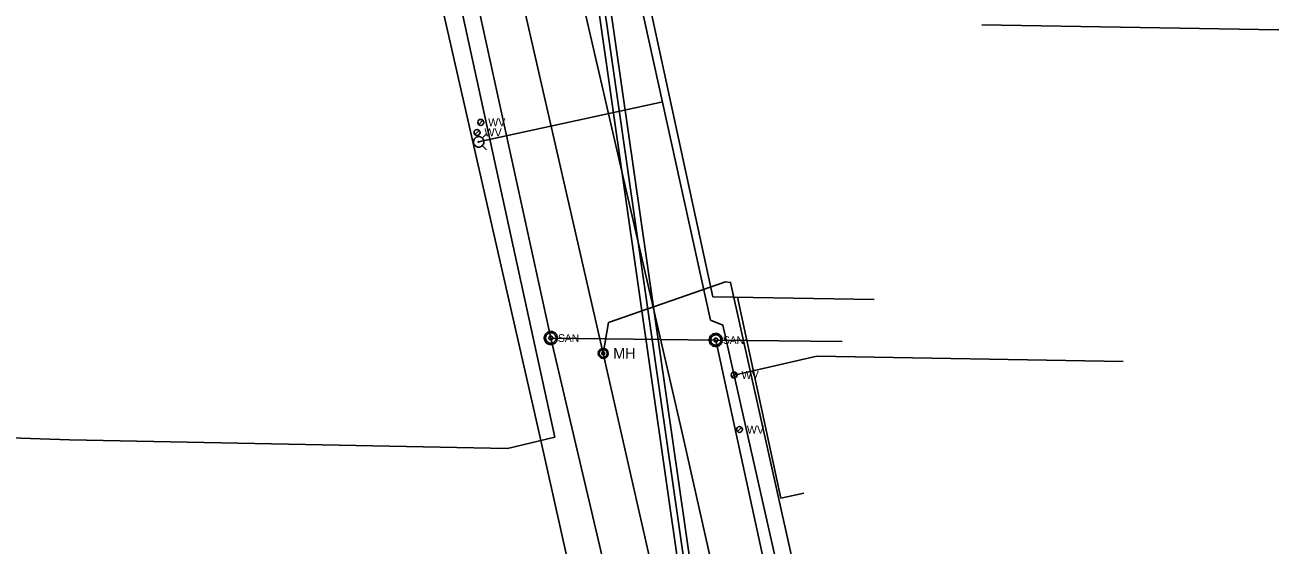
# Model space of a CAD drawing. Extents: x 596028 to 606371, y 330010 to 403088.
# Drawn here: x 604586 to 605210, y 338728 to 338989 of the extents above; entities that cross this region are included whole.
import ezdxf

# ---------------------------------------------------------------- set-up
doc = ezdxf.new("R2010")
doc.units = 0
for name, color, linetype in [('Default', 7, 'Continuous'), ('E_UTL_E', 7, 'Continuous'), ('E_UTL_E_UG', 7, 'Continuous'), ('E_UTL_G_UG', 7, 'Continuous'), ('E_UTL_Overhead', 7, 'Continuous'), ('E_UTL_SAN_MH', 7, 'Continuous'), ('E_UTL_SAN_UG', 7, 'Continuous'), ('E_UTL_SAN_UG_MMSD', 7, 'Continuous'), ('E_UTL_SAN_UG_OUTER_LIMITS', 7, 'Continuous'), ('E_UTL_T_UG', 7, 'Continuous'), ('E_UTL_TV_UG', 7, 'Continuous'), ('E_UTL_W', 7, 'Continuous'), ('E_UTL_W_UG', 7, 'Continuous'), ('E_UTL_WHydrant', 7, 'Continuous')]:
    doc.layers.add(name, color=color, linetype=linetype)

# ---------------------------------------------------------------- blocks, each defined once
blk = doc.blocks.new('MH')
at = {"layer": 'Default'}
for radius in [15.2, 12.2, 4.57]:
    blk.add_circle((0, 0), radius, dxfattribs=at)
blk.add_text('MH', height=32.92, dxfattribs=at).set_placement((30.5, -16.5))
blk = doc.blocks.new('WV')
at = {"layer": 'E_UTL_W'}
blk.add_line((-8.6, -8.6), (8.6, 8.6), dxfattribs=at)
blk.add_circle((0, 0), 12.2, dxfattribs=at)
blk.add_text('WV', height=32.92, dxfattribs=at).set_placement((30.5, -16.5))

msp = doc.modelspace()

# ---------------------------------------------------------------- linework, layer by layer
at = {"layer": 'E_UTL_E_UG'}
for p, q in [((604875.51, 338824.32), (604784.34, 339222.62)), ((604977.34, 338376.34), (604875.51, 338824.32))]:
    msp.add_line(p, q, dxfattribs=at)
msp.add_lwpolyline([(604875.51, 338824.32), (604878.17, 338839.74), (604936.85, 338860.21)], dxfattribs=at)
at = {"layer": 'E_UTL_G_UG'}
for p, q in [((604843.56, 338783.61), (604742.35, 339228.68)), ((604914.69, 338786.08), (604814.85, 339218.78)), ((604930.39, 338852.74), (605011.23, 338851.4)), ((605063.85, 338123.62), (604914.69, 338786.08))]:
    msp.add_line(p, q, dxfattribs=at)
for points in [[(604930.39, 338852.74), (604855.87, 339196.73), (604848.74, 339224.99)], [(604975.97, 338754.36), (604964.55, 338751.87), (604942.74, 338852.53)], [(604985.44, 338110.91), (604985.58, 338148.1), (604843.56, 338783.61)]]:
    msp.add_lwpolyline(points, dxfattribs=at)
at = {"layer": 'E_UTL_Overhead'}
msp.add_line((605065.21, 338988.93), (605529.98, 338981.15), dxfattribs=at)
at = {"layer": 'E_UTL_SAN_MH'}
for points in [[(604852.55, 338832.04), (604852.49, 338832.66), (604852.32, 338833.26), (604852.03, 338833.82), (604851.64, 338834.32), (604851.17, 338834.73), (604850.62, 338835.04), (604850.03, 338835.24), (604849.41, 338835.33), (604848.78, 338835.3), (604848.17, 338835.16), (604847.6, 338834.9), (604847.09, 338834.53), (604846.66, 338834.08), (604846.32, 338833.55), (604846.09, 338832.97), (604845.97, 338832.35), (604845.97, 338831.72), (604846.09, 338831.11), (604846.32, 338830.53), (604846.66, 338830), (604847.09, 338829.54), (604847.6, 338829.18), (604848.17, 338828.92), (604848.78, 338828.77), (604849.41, 338828.74), (604850.03, 338828.83), (604850.62, 338829.04), (604851.17, 338829.35), (604851.64, 338829.76), (604852.03, 338830.25), (604852.32, 338830.81), (604852.49, 338831.41), (604852.55, 338832.04)], [(604851.89, 338832.04), (604851.84, 338832.54), (604851.7, 338833.02), (604851.47, 338833.47), (604851.16, 338833.86), (604850.78, 338834.19), (604850.35, 338834.44), (604849.87, 338834.6), (604849.38, 338834.67), (604848.88, 338834.65), (604848.39, 338834.53), (604847.93, 338834.32), (604847.52, 338834.03), (604847.18, 338833.67), (604846.91, 338833.25), (604846.72, 338832.78), (604846.62, 338832.29), (604846.62, 338831.79), (604846.72, 338831.29), (604846.91, 338830.83), (604847.18, 338830.41), (604847.52, 338830.04), (604847.93, 338829.75), (604848.39, 338829.54), (604848.88, 338829.42), (604849.38, 338829.4), (604849.87, 338829.47), (604850.35, 338829.64), (604850.78, 338829.89), (604851.16, 338830.22), (604851.47, 338830.61), (604851.7, 338831.06), (604851.84, 338831.54), (604851.89, 338832.04)], [(604935.22, 338831.04), (604935.16, 338831.66), (604934.98, 338832.27), (604934.69, 338832.82), (604934.3, 338833.32), (604933.83, 338833.73), (604933.29, 338834.04), (604932.69, 338834.25), (604932.07, 338834.34), (604931.45, 338834.31), (604930.84, 338834.16), (604930.27, 338833.9), (604929.75, 338833.53), (604929.32, 338833.08), (604928.98, 338832.55), (604928.75, 338831.97), (604928.63, 338831.35), (604928.63, 338830.73), (604928.75, 338830.11), (604928.98, 338829.53), (604929.32, 338829), (604929.75, 338828.55), (604930.27, 338828.18), (604930.84, 338827.92), (604931.45, 338827.77), (604932.07, 338827.74), (604932.69, 338827.83), (604933.29, 338828.04), (604933.83, 338828.35), (604934.3, 338828.76), (604934.69, 338829.26), (604934.98, 338829.81), (604935.16, 338830.41), (604935.22, 338831.04)], [(604934.56, 338831.04), (604934.51, 338831.54), (604934.37, 338832.02), (604934.14, 338832.47), (604933.83, 338832.86), (604933.45, 338833.19), (604933.01, 338833.44), (604932.54, 338833.6), (604932.04, 338833.68), (604931.54, 338833.65), (604931.05, 338833.53), (604930.6, 338833.33), (604930.19, 338833.03), (604929.84, 338832.67), (604929.57, 338832.25), (604929.38, 338831.78), (604929.29, 338831.29), (604929.29, 338830.79), (604929.38, 338830.3), (604929.57, 338829.83), (604929.84, 338829.41), (604930.19, 338829.04), (604930.6, 338828.75), (604931.05, 338828.54), (604931.54, 338828.43), (604932.04, 338828.4), (604932.54, 338828.47), (604933.01, 338828.64), (604933.45, 338828.89), (604933.83, 338829.22), (604934.14, 338829.61), (604934.37, 338830.06), (604934.51, 338830.54), (604934.56, 338831.04)], [(604850.24, 338832.04), (604850.22, 338832.23), (604850.17, 338832.41), (604850.09, 338832.57), (604849.97, 338832.72), (604849.83, 338832.84), (604849.66, 338832.94), (604849.49, 338833), (604849.3, 338833.03), (604849.11, 338833.02), (604848.93, 338832.97), (604848.76, 338832.9), (604848.6, 338832.79), (604848.47, 338832.65), (604848.37, 338832.49), (604848.3, 338832.32), (604848.27, 338832.13), (604848.27, 338831.94), (604848.3, 338831.76), (604848.37, 338831.58), (604848.47, 338831.43), (604848.6, 338831.29), (604848.76, 338831.18), (604848.93, 338831.1), (604849.11, 338831.06), (604849.3, 338831.05), (604849.49, 338831.08), (604849.66, 338831.14), (604849.83, 338831.23), (604849.97, 338831.35), (604850.09, 338831.5), (604850.17, 338831.67), (604850.22, 338831.85), (604850.24, 338832.04)], [(604932.91, 338831.04), (604932.89, 338831.23), (604932.83, 338831.41), (604932.75, 338831.57), (604932.63, 338831.72), (604932.49, 338831.85), (604932.33, 338831.94), (604932.15, 338832), (604931.96, 338832.03), (604931.78, 338832.02), (604931.59, 338831.97), (604931.42, 338831.9), (604931.27, 338831.79), (604931.14, 338831.65), (604931.04, 338831.49), (604930.97, 338831.32), (604930.93, 338831.13), (604930.93, 338830.95), (604930.97, 338830.76), (604931.04, 338830.59), (604931.14, 338830.43), (604931.27, 338830.29), (604931.42, 338830.18), (604931.59, 338830.1), (604931.78, 338830.06), (604931.96, 338830.05), (604932.15, 338830.08), (604932.33, 338830.14), (604932.49, 338830.23), (604932.63, 338830.36), (604932.75, 338830.5), (604932.83, 338830.67), (604932.89, 338830.85), (604932.91, 338831.04)]]:
    msp.add_lwpolyline(points, dxfattribs=at)
at = {"layer": 'E_UTL_SAN_UG'}
for p, q in [((604849.24, 338832.01), (604802.36, 339046.2)), ((604849.24, 338832.01), (604931.92, 338831.04)), ((604883.17, 338687.37), (604849.24, 338832.01)), ((604931.92, 338831.04), (604995.25, 338830.29)), ((604979.45, 338612.08), (604931.92, 338831.04))]:
    msp.add_line(p, q, dxfattribs=at)
at = {"layer": 'E_UTL_SAN_UG_MMSD'}
msp.add_line((605016.2, 338023.67), (604854.51, 339147.21), dxfattribs=at)
at = {"layer": 'E_UTL_SAN_UG_OUTER_LIMITS'}
for p, q in [((605012.73, 338026.74), (604851.55, 339146.7)), ((605019.67, 338020.62), (604857.47, 339147.72))]:
    msp.add_line(p, q, dxfattribs=at)
at = {"layer": 'E_UTL_T_UG'}
msp.add_line((604851.26, 338782.4), (604759.41, 339203.92), dxfattribs=at)
for points in [[(604481.71, 338582.68), (604483.97, 338760.08), (604484.94, 338767.82), (604486.38, 338775.38), (604487.85, 338777.99), (604490.94, 338781.48), (604495.94, 338783.91), (604536.09, 338781.88), (604555.81, 338781.9), (604562.17, 338782.36), (604565.94, 338783.42), (604578.66, 338781.98), (604607.98, 338781)], [(604607.98, 338781), (604827.54, 338776.75), (604851.26, 338782.4)]]:
    msp.add_lwpolyline(points, dxfattribs=at)
at = {"layer": 'E_UTL_TV_UG'}
msp.add_lwpolyline([(605091.46, 338177.8), (604939.3, 338859.88), (604936.85, 338860.21)], dxfattribs=at)
at = {"layer": 'E_UTL_W_UG'}
for p, q in [((604813.06, 338930.32), (604905.42, 338950.46)), ((604941.09, 338813.5), (604982.61, 338822.87)), ((604982.61, 338822.87), (605136.11, 338820.33))]:
    msp.add_line(p, q, dxfattribs=at)
msp.add_lwpolyline([(605092.03, 338144.65), (604935.52, 338838.52), (604929.29, 338841.05), (604874.71, 339088.99)], dxfattribs=at)
at = {"layer": 'E_UTL_WHydrant'}
for points in [[(604813.06, 338927.69), (604813.56, 338927.74), (604814.03, 338927.88), (604814.48, 338928.11), (604814.87, 338928.42), (604815.2, 338928.79), (604815.45, 338929.23), (604815.61, 338929.7), (604815.68, 338930.19), (604815.66, 338930.69), (604815.54, 338931.17), (604815.33, 338931.63), (604815.04, 338932.03), (604814.68, 338932.38), (604814.26, 338932.65), (604813.8, 338932.83), (604813.31, 338932.93), (604812.81, 338932.93), (604812.32, 338932.83), (604811.86, 338932.65), (604811.44, 338932.38), (604811.08, 338932.03), (604810.79, 338931.63), (604810.58, 338931.17), (604810.46, 338930.69), (604810.44, 338930.19), (604810.51, 338929.7), (604810.67, 338929.23), (604810.92, 338928.79), (604811.25, 338928.42), (604811.64, 338928.11), (604812.09, 338927.88), (604812.56, 338927.74), (604813.06, 338927.69)], [(604814.9, 338932.15), (604817.04, 338934.29)], [(604813.06, 338930.12), (604813.1, 338930.12), (604813.13, 338930.13), (604813.17, 338930.15), (604813.2, 338930.17), (604813.22, 338930.2), (604813.24, 338930.23), (604813.26, 338930.27), (604813.26, 338930.31), (604813.26, 338930.34), (604813.25, 338930.38), (604813.23, 338930.42), (604813.21, 338930.45), (604813.18, 338930.47), (604813.15, 338930.49), (604813.12, 338930.51), (604813.08, 338930.52), (604813.04, 338930.52), (604813, 338930.51), (604812.97, 338930.49), (604812.94, 338930.47), (604812.91, 338930.45), (604812.89, 338930.42), (604812.87, 338930.38), (604812.86, 338930.34), (604812.86, 338930.31), (604812.87, 338930.27), (604812.88, 338930.23), (604812.9, 338930.2), (604812.92, 338930.17), (604812.95, 338930.15), (604812.99, 338930.13), (604813.02, 338930.12), (604813.06, 338930.12)], [(604814.9, 338928.48), (604817.04, 338926.34)]]:
    msp.add_lwpolyline(points, dxfattribs=at)

# ---------------------------------------------------------------- block references
at = {"layer": 'E_UTL_E', "xscale": 0.16404166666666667, "yscale": 0.16404166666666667}
msp.add_blockref('MH', (604875.51, 338824.32), dxfattribs=at)
at = {"layer": 'E_UTL_W', "xscale": 0.12188295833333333, "yscale": 0.12188295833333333}
for p in [(604814.12, 338940.09), (604812.26, 338935.05), (604941.09, 338813.5), (604943.77, 338786.17)]:
    msp.add_blockref('WV', p, dxfattribs=at)

# ---------------------------------------------------------------- texts
at = {"layer": 'E_UTL_SAN_MH'}
for p in [(604852.82, 338830.09), (604935.48, 338829.09)]:
    msp.add_text('SAN', height=3.849, dxfattribs=at).set_placement(p)

doc.saveas('drawing.dxf')
